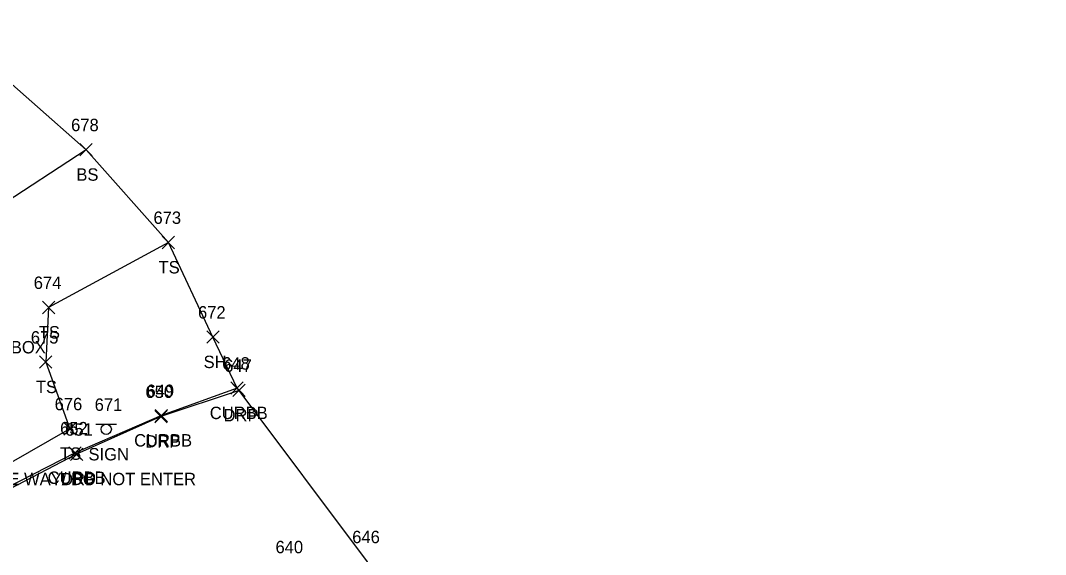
# Model space of a CAD drawing. Extents: x 1623612 to 1625808, y 621345 to 627748.
# Drawn here: x 1625034.6 to 1625200.2, y 626016.7 to 626102.9 of the extents above; entities that cross this region are included whole.
import ezdxf

# ---------------------------------------------------------------- set-up
doc = ezdxf.new("R2010")
doc.units = 0
for name, color, linetype in [('L_A', 7, 'Continuous'), ('L_I', 7, 'Continuous'), ('L_TIC', 7, 'Continuous'), ('LELB', 7, 'Continuous'), ('LSOGP', 7, 'Continuous'), ('R_A', 7, 'Continuous'), ('R_I', 7, 'Continuous'), ('R_TIC', 7, 'Continuous'), ('RC', 7, 'Continuous'), ('RDP', 7, 'Continuous'), ('S_A', 7, 'Continuous'), ('S_C', 7, 'Continuous'), ('S_I', 7, 'Continuous'), ('SSGN', 7, 'Continuous'), ('U_C', 7, 'Continuous')]:
    doc.layers.add(name, color=color, linetype=linetype)

msp = doc.modelspace()

# ---------------------------------------------------------------- linework, layer by layer
at = {"layer": 'L_TIC'}
for points in [[(1625044.18, 626081.05), (1625046.18, 626083.05)], [(1625046.18, 626081.05), (1625044.18, 626083.05)], [(1625057.49, 626066.08), (1625059.49, 626068.08)], [(1625059.49, 626066.08), (1625057.49, 626068.08)], [(1625038.14, 626055.58), (1625040.14, 626057.58)], [(1625040.14, 626055.58), (1625038.14, 626057.58)], [(1625064.69, 626050.8), (1625066.69, 626052.8)], [(1625066.69, 626050.8), (1625064.69, 626052.8)], [(1625037.67, 626046.76), (1625039.67, 626048.76)], [(1625039.67, 626046.76), (1625037.67, 626048.76)], [(1625041.58, 626035.99), (1625043.58, 626037.99)], [(1625043.58, 626035.99), (1625041.58, 626037.99)]]:
    msp.add_lwpolyline(points, dxfattribs=at)
at = {"layer": 'LELB'}
for points in [[(1625045.18, 626082.05), (1625030.64, 626072.55), (1625024.54, 626062.35), (1625026.8, 626052.15), (1625032.19, 626038.09), (1625026.04, 626032.14)], [(1625058.49, 626067.08), (1625039.14, 626056.58), (1625038.67, 626047.76), (1625042.58, 626036.99), (1625029.39, 626029.44), (1625024.48, 626025.16)]]:
    msp.add_lwpolyline(points, dxfattribs=at)
at = {"layer": 'LSOGP'}
msp.add_lwpolyline([(1625200.23, 625842.69), (1625180.7, 625879.29), (1625153.81, 625905.72), (1625139.96, 625942.2), (1625106.19, 625988.13), (1625099.02, 625990.77), (1625092.97, 625994.26), (1625089.75, 626000.84), (1625088.99, 626008.69), (1625090.67, 626015.53), (1625069.92, 626043.19), (1625069.59, 626043.56), (1625065.69, 626051.8), (1625058.49, 626067.08), (1625045.18, 626082.05), (1625027.59, 626097.53), (1625025.64, 626131.89)], dxfattribs=at)
at = {"layer": 'R_TIC'}
for points in [[(1625068.59, 626042.56), (1625070.59, 626044.56)], [(1625070.59, 626042.56), (1625068.59, 626044.56)], [(1625068.92, 626042.19), (1625070.92, 626044.19)], [(1625070.92, 626042.19), (1625068.92, 626044.19)], [(1625056.28, 626037.97), (1625058.28, 626039.97)], [(1625058.28, 626037.97), (1625056.28, 626039.97)], [(1625056.37, 626038.13), (1625058.37, 626040.13)], [(1625058.37, 626038.13), (1625056.37, 626040.13)], [(1625042.4, 626032.1), (1625044.4, 626034.1)], [(1625044.4, 626032.1), (1625042.4, 626034.1)], [(1625042.66, 626031.88), (1625044.66, 626033.88)], [(1625044.66, 626031.88), (1625042.66, 626033.88)]]:
    msp.add_lwpolyline(points, dxfattribs=at)
at = {"layer": 'RC'}
msp.add_lwpolyline([(1625069.59, 626043.56), (1625057.37, 626039.13), (1625043.4, 626033.1), (1625027.69, 626025.1), (1625023.16, 626022.93)], dxfattribs=at)
at = {"layer": 'RDP'}
msp.add_lwpolyline([(1625069.92, 626043.19), (1625057.28, 626038.97), (1625043.66, 626032.88), (1625027.93, 626024.71), (1625022.95, 626022.12), (1625020.92, 626020.71), (1625015.97, 626018.8), (1625013.33, 626018.3), (1625006.51, 626020.44)], dxfattribs=at)
at = {"layer": 'SSGN'}
for p, q in [((1625046.79, 626037.75), (1625050.13, 626037.75)), ((1625048.44, 626036.91), (1625048.44, 626036.91))]:
    msp.add_line(p, q, dxfattribs=at)
msp.add_circle((1625048.44, 626036.91), 0.833, dxfattribs=at)

# ---------------------------------------------------------------- texts
at = {"layer": 'L_A'}
for s, p in [('BS', (1625043.62, 626077.05)), ('TS', (1625056.9, 626062.08)), ('TS', (1625037.55, 626051.58)), ('SH', (1625064.18, 626046.8)), ('TS', (1625037.08, 626042.76)), ('TS', (1625040.99, 626031.99))]:
    msp.add_text(s, height=2, dxfattribs=at).set_placement(p)
at = {"layer": 'L_I'}
for s, p in [('678', (1625042.77, 626085.05)), ('673', (1625056.08, 626070.08)), ('674', (1625036.73, 626059.58)), ('672', (1625063.28, 626054.8)), ('675', (1625036.26, 626050.76)), ('676', (1625040.11, 626039.99)), ('640', (1625075.8, 626016.9))]:
    msp.add_text(s, height=2, dxfattribs=at).set_placement(p)
at = {"layer": 'R_A'}
for s, p in [('CURBB', (1625065.18, 626038.56)), ('DRP', (1625067.41, 626038.19)), ('CURBB', (1625052.96, 626034.13)), ('DRP', (1625054.76, 626033.97)), ('CURBB', (1625038.98, 626028.1)), ('DRP', (1625041.15, 626027.88))]:
    msp.add_text(s, height=2, dxfattribs=at).set_placement(p)
at = {"layer": 'R_I'}
for s, p in [('648', (1625067.18, 626046.56)), ('647', (1625067.51, 626046.19)), ('649', (1625054.96, 626042.13)), ('650', (1625054.78, 626041.97)), ('652', (1625040.99, 626036.1)), ('651', (1625041.81, 626035.88)), ('646', (1625088.2, 626018.53))]:
    msp.add_text(s, height=2, dxfattribs=at).set_placement(p)
at = {"layer": 'S_A'}
msp.add_text('SIGN', height=2, dxfattribs=at).set_placement((1625045.58, 626031.89))
at = {"layer": 'S_C'}
msp.add_text('ONE WAY/ DO NOT ENTER', height=2, dxfattribs=at).set_placement((1625028.63, 626027.89))
at = {"layer": 'S_I'}
msp.add_text('671', height=2, dxfattribs=at).set_placement((1625046.58, 626039.89))
at = {"layer": 'U_C'}
msp.add_text('TELEPHONE JUNCTION BOX', height=2, dxfattribs=at).set_placement((1625001.83, 626049.17))

doc.saveas('drawing.dxf')
